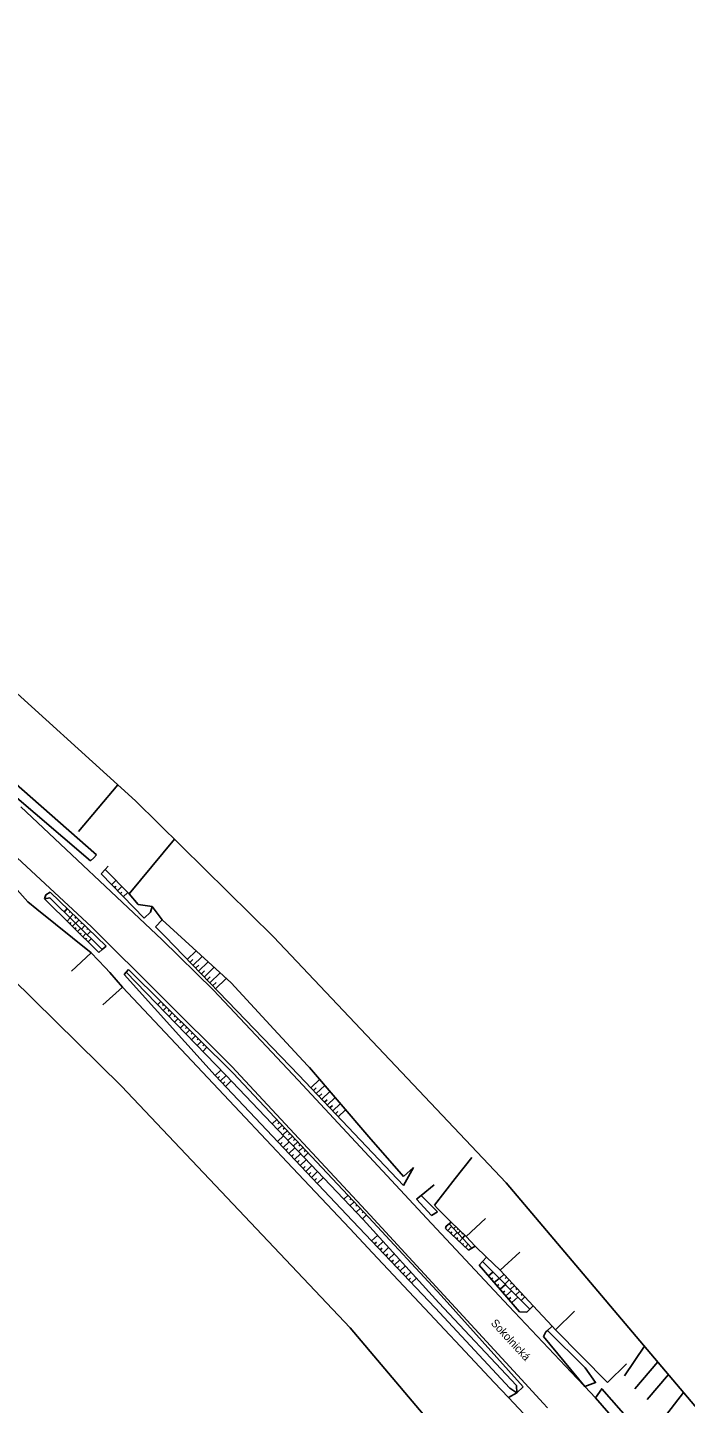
# Model space of a CAD drawing. Extents: x -594451 to -591069, y -1167621 to -1167156.
# Drawn here: x -594264.9 to -594141.4, y -1167414.2 to -1167156.3 of the extents above; entities that cross this region are included whole.
import ezdxf

# ---------------------------------------------------------------- set-up
doc = ezdxf.new("R2010")
doc.units = 0
doc.layers.add('MAPA', color=7, linetype='Continuous')
doc.layers.add('Žádosti', color=7, linetype='Continuous')

msp = doc.modelspace()

# ---------------------------------------------------------------- linework, layer by layer
at = {"layer": 'MAPA'}
for p, q in [((-594247.93, -1167298.31), (-594255.36, -1167307.05)), ((-594245.85, -1167318.7), (-594237.33, -1167308.46)), ((-594152.86, -1167409.05), (-594149.13, -1167403.52)), ((-594150.98, -1167411.48), (-594146.66, -1167406.43)), ((-594144.63, -1167408.84), (-594148.62, -1167413.5)), ((-594145.22, -1167416.56), (-594141.8, -1167412.17))]:
    msp.add_line(p, q, dxfattribs=at)
for points in [[(-594251.95, -1167311.42), (-594267.55, -1167297.72), (-594273.49, -1167293.36), (-594286.83, -1167282.42), (-594286.11, -1167279.61)], [(-594268.63, -1167299.2), (-594253.06, -1167312.5)], [(-594239.69, -1167327.27), (-594266.17, -1167302.4)], [(-594271.2, -1167307.95), (-594252.89, -1167324.93)], [(-594253.06, -1167312.5), (-594252.48, -1167311.94)], [(-594252.48, -1167311.94), (-594251.95, -1167311.42)], [(-594250.33, -1167314.14), (-594251.11, -1167314.98)], [(-594251.11, -1167314.98), (-594243.04, -1167323.26)], [(-594249.74, -1167313.5), (-594250.33, -1167314.14)], [(-594250.33, -1167314.14), (-594245.85, -1167318.7)], [(-594264.81, -1167320.21), (-594266.87, -1167317.96)], [(-594248.31, -1167316.2), (-594249.13, -1167317.01)], [(-594248.31, -1167317.3), (-594248.59, -1167317.57)], [(-594247.2, -1167317.32), (-594248.04, -1167318.13)], [(-594264.81, -1167320.21), (-594263.14, -1167321.56), (-594252.98, -1167329.77)], [(-594261.49, -1167318.88), (-594261.7, -1167319.64)], [(-594260.73, -1167319.48), (-594261.7, -1167319.64)], [(-594261.7, -1167319.64), (-594251.52, -1167329.72)], [(-594260.64, -1167318.42), (-594261.49, -1167318.88)], [(-594250.89, -1167329.17), (-594260.73, -1167319.48)], [(-594250.13, -1167328.52), (-594260.64, -1167318.42)], [(-594247.21, -1167318.43), (-594247.49, -1167318.7)], [(-594246.1, -1167318.44), (-594246.94, -1167319.26)], [(-594245.85, -1167318.7), (-594244.11, -1167320.73)], [(-594244.11, -1167320.73), (-594241.54, -1167321.08)], [(-594258.05, -1167322.12), (-594257.45, -1167321.49)], [(-594256.91, -1167323.24), (-594257.48, -1167323.82)], [(-594257.1, -1167322.23), (-594256.9, -1167322.02)], [(-594256.96, -1167323.19), (-594256.34, -1167322.55)], [(-594256, -1167323.3), (-594255.79, -1167323.08)], [(-594243.04, -1167323.26), (-594241.81, -1167322.16)], [(-594241.81, -1167322.16), (-594241.54, -1167321.08)], [(-594239.66, -1167323.56), (-594241.54, -1167321.08)], [(-594256.8, -1167324.11), (-594256.99, -1167324.31)], [(-594255.92, -1167324.22), (-594256.49, -1167324.8)], [(-594255.8, -1167325.1), (-594256, -1167325.29)], [(-594255.87, -1167324.27), (-594255.24, -1167323.61)], [(-594254.93, -1167325.2), (-594255.5, -1167325.78)], [(-594254.9, -1167324.36), (-594254.69, -1167324.14)], [(-594254.78, -1167325.34), (-594254.13, -1167324.67)], [(-594253.8, -1167325.43), (-594253.58, -1167325.2)], [(-594253.68, -1167326.42), (-594253.03, -1167325.74)], [(-594252.89, -1167324.93), (-594226.57, -1167351.07)], [(-594239.66, -1167323.56), (-594240.9, -1167324.9)], [(-594240.9, -1167324.9), (-594239.04, -1167326.8)], [(-594239.66, -1167323.56), (-594226.69, -1167335.41)], [(-594254.81, -1167326.07), (-594255.01, -1167326.27)], [(-594253.93, -1167326.17), (-594254.51, -1167326.76)], [(-594253.82, -1167327.05), (-594254.02, -1167327.25)], [(-594252.94, -1167327.15), (-594253.52, -1167327.74)], [(-594250.89, -1167329.17), (-594250.13, -1167328.52)], [(-594230.02, -1167336.78), (-594239.69, -1167327.27)], [(-594239.04, -1167326.8), (-594213.98, -1167352.73)], [(-594256.62, -1167333.19), (-594252.98, -1167329.77)], [(-594252.98, -1167329.77), (-594250.3, -1167332.52)], [(-594251.52, -1167329.72), (-594250.89, -1167329.17)], [(-594233.28, -1167329.39), (-594234.96, -1167331.02)], [(-594233.86, -1167331.02), (-594234.43, -1167331.57)], [(-594232.15, -1167330.43), (-594233.9, -1167332.12)], [(-594249.47, -1167333.48), (-594250.3, -1167332.52)], [(-594249.47, -1167333.48), (-594247.06, -1167336.19)], [(-594246.41, -1167333.4), (-594246.75, -1167333.81)], [(-594245.97, -1167332.89), (-594246.41, -1167333.4)], [(-594227.7, -1167352.71), (-594246.41, -1167333.4)], [(-594226.29, -1167352.34), (-594245.97, -1167332.89)], [(-594232.77, -1167332.09), (-594233.37, -1167332.67)], [(-594231.01, -1167331.46), (-594232.84, -1167333.22)], [(-594231.69, -1167333.17), (-594232.3, -1167333.77)], [(-594229.88, -1167332.49), (-594231.77, -1167334.32)], [(-594228.75, -1167333.53), (-594230.71, -1167335.42)], [(-594250.8, -1167339.51), (-594247.06, -1167336.19)], [(-594247.06, -1167336.19), (-594238.07, -1167345.74)], [(-594229.7, -1167352.75), (-594246.75, -1167333.81)], [(-594230.6, -1167334.25), (-594231.24, -1167334.87)], [(-594229.51, -1167335.33), (-594230.18, -1167335.97)], [(-594227.62, -1167334.56), (-594229.65, -1167336.52)], [(-594226.69, -1167335.41), (-594218.67, -1167344.08)], [(-594240.5, -1167339.5), (-594239.9, -1167338.89)], [(-594214.12, -1167353.64), (-594230.02, -1167336.78)], [(-594239.56, -1167339.64), (-594239.35, -1167339.43)], [(-594239.44, -1167340.6), (-594238.81, -1167339.97)], [(-594238.48, -1167340.72), (-594238.27, -1167340.5)], [(-594238.38, -1167341.69), (-594237.73, -1167341.04)], [(-594237.41, -1167341.79), (-594237.19, -1167341.57)], [(-594237.31, -1167342.79), (-594236.64, -1167342.11)], [(-594236.33, -1167342.87), (-594236.1, -1167342.64)], [(-594236.26, -1167343.88), (-594235.56, -1167343.18)], [(-594235.25, -1167343.95), (-594235.02, -1167343.71)], [(-594218.67, -1167344.08), (-594212.34, -1167350.88)], [(-594238.07, -1167345.74), (-594225.06, -1167359.57)], [(-594235.19, -1167344.97), (-594234.48, -1167344.25)], [(-594234.18, -1167345.03), (-594233.94, -1167344.78)], [(-594234.14, -1167346.07), (-594233.39, -1167345.32)], [(-594233.1, -1167346.11), (-594232.85, -1167345.86)], [(-594233.07, -1167347.16), (-594232.31, -1167346.39)], [(-594232.03, -1167347.19), (-594231.77, -1167346.93)], [(-594232.01, -1167348.26), (-594231.23, -1167347.46)], [(-594228.63, -1167351.74), (-594229.7, -1167352.75)], [(-594226.57, -1167351.07), (-594200.58, -1167378.94)], [(-594212.34, -1167350.88), (-594212.01, -1167351.27)], [(-594212.01, -1167351.27), (-594200.89, -1167364.28)], [(-594203.93, -1167379.99), (-594229.7, -1167352.75)], [(-594228.85, -1167352.93), (-594229.21, -1167353.27)], [(-594227.65, -1167352.76), (-594228.72, -1167353.78)], [(-594227.88, -1167353.96), (-594228.24, -1167354.3)], [(-594226.67, -1167353.79), (-594227.75, -1167354.81)], [(-594201.94, -1167379.75), (-594227.7, -1167352.71)], [(-594200.83, -1167379.37), (-594226.29, -1167352.34)], [(-594190, -1167379.57), (-594214.12, -1167353.64)], [(-594213.98, -1167352.73), (-594194.36, -1167373.39)], [(-594210.11, -1167353.49), (-594211.77, -1167355.06)], [(-594210.71, -1167355.09), (-594211.25, -1167355.6)], [(-594209.14, -1167354.63), (-594210.74, -1167356.15)], [(-594209.7, -1167356.19), (-594210.22, -1167356.69)], [(-594208.16, -1167355.77), (-594209.7, -1167357.23)], [(-594207.19, -1167356.91), (-594208.67, -1167358.32)], [(-594225.06, -1167359.57), (-594215.16, -1167370.1)], [(-594208.69, -1167357.3), (-594209.19, -1167357.77)], [(-594207.67, -1167358.4), (-594208.16, -1167358.86)], [(-594206.22, -1167358.05), (-594207.64, -1167359.4)], [(-594206.66, -1167359.5), (-594207.13, -1167359.95)], [(-594205.24, -1167359.19), (-594206.61, -1167360.49)], [(-594219, -1167361.84), (-594218.12, -1167361.01)], [(-594218.01, -1167362.88), (-594217.14, -1167362.06)], [(-594217.92, -1167361.81), (-594217.63, -1167361.53)], [(-594216.89, -1167364.06), (-594218.01, -1167365.11)], [(-594217.02, -1167363.92), (-594216.15, -1167363.1)], [(-594216.94, -1167362.85), (-594216.65, -1167362.58)], [(-594216.03, -1167364.96), (-594215.17, -1167364.14)], [(-594215.95, -1167363.89), (-594215.66, -1167363.62)], [(-594214.97, -1167364.94), (-594214.68, -1167364.67)], [(-594200.89, -1167364.28), (-594194.38, -1167371.72)], [(-594217.1, -1167365.32), (-594217.47, -1167365.68)], [(-594215.82, -1167365.18), (-594216.94, -1167366.24)], [(-594216.03, -1167366.45), (-594216.41, -1167366.8)], [(-594214.75, -1167366.3), (-594215.87, -1167367.37)], [(-594215.05, -1167365.99), (-594214.19, -1167365.19)], [(-594214.06, -1167367.03), (-594213.21, -1167366.23)], [(-594213.98, -1167365.98), (-594213.7, -1167365.71)], [(-594213.07, -1167368.07), (-594212.22, -1167367.27)], [(-594213, -1167367.02), (-594212.71, -1167366.75)], [(-594214.97, -1167367.57), (-594215.34, -1167367.93)], [(-594213.68, -1167367.43), (-594214.81, -1167368.49)], [(-594213.9, -1167368.7), (-594214.28, -1167369.05)], [(-594212.61, -1167368.55), (-594213.74, -1167369.62)], [(-594212.83, -1167369.82), (-594213.21, -1167370.18)], [(-594211.54, -1167369.67), (-594212.68, -1167370.74)], [(-594184.63, -1167372.05), (-594181.54, -1167368.12)], [(-594215.16, -1167370.1), (-594204.45, -1167381.47)], [(-594211.77, -1167370.95), (-594212.14, -1167371.31)], [(-594210.47, -1167370.79), (-594211.61, -1167371.87)], [(-594210.7, -1167372.07), (-594211.08, -1167372.43)], [(-594209.4, -1167371.92), (-594210.55, -1167373)], [(-594194.38, -1167371.72), (-594192.46, -1167370.01)], [(-594194.36, -1167373.39), (-594192.46, -1167370.01)], [(-594188.56, -1167377.06), (-594184.63, -1167372.05)], [(-594188.6, -1167373.24), (-594191.03, -1167375.24)], [(-594205.56, -1167375.95), (-594204.76, -1167375.19)], [(-594204.45, -1167376.06), (-594204.18, -1167375.81)], [(-594204.4, -1167377.17), (-594203.6, -1167376.43)], [(-594203.28, -1167377.29), (-594203.02, -1167377.04)], [(-594191.03, -1167375.24), (-594191.91, -1167375.96)], [(-594191.91, -1167375.96), (-594189.07, -1167379.02)], [(-594191.03, -1167375.24), (-594187.96, -1167378.31)], [(-594187.97, -1167377.72), (-594188.56, -1167377.06)], [(-594188.4, -1167396.29), (-594203.93, -1167379.99)], [(-594203.23, -1167378.4), (-594202.44, -1167377.66)], [(-594202.12, -1167378.52), (-594201.86, -1167378.28)], [(-594202.06, -1167379.63), (-594201.28, -1167378.89)], [(-594187.71, -1167395.36), (-594201.94, -1167379.75)], [(-594187.3, -1167394), (-594200.83, -1167379.37)], [(-594200.58, -1167378.94), (-594171.51, -1167410.53)], [(-594161.82, -1167409.49), (-594174.58, -1167396.03), (-594190, -1167379.57)], [(-594189.07, -1167379.02), (-594187.96, -1167378.31)], [(-594187.97, -1167377.72), (-594185.41, -1167380.26)], [(-594182.61, -1167382.95), (-594178.94, -1167379.55)], [(-594204.45, -1167381.47), (-594200.18, -1167386.01)], [(-594199.23, -1167382.73), (-594200.33, -1167383.77)], [(-594186.32, -1167381), (-594186.45, -1167381.42)], [(-594186.45, -1167381.42), (-594182.15, -1167385.54)], [(-594185.81, -1167380.59), (-594186.32, -1167381)], [(-594185.35, -1167381.08), (-594186.05, -1167381.81)], [(-594185.41, -1167380.26), (-594185.81, -1167380.59)], [(-594185.81, -1167380.59), (-594181.52, -1167385.13)], [(-594185.27, -1167382.1), (-594185.5, -1167382.33)], [(-594182.61, -1167382.95), (-594185.41, -1167380.26)], [(-594184.96, -1167381.49), (-594184.56, -1167381.07)], [(-594184.3, -1167382.18), (-594184.95, -1167382.86)], [(-594184.27, -1167381.64), (-594184.13, -1167381.49)], [(-594184.13, -1167382.37), (-594183.69, -1167381.91)], [(-594183.41, -1167382.49), (-594183.25, -1167382.33)], [(-594183.3, -1167383.25), (-594182.82, -1167382.75)], [(-594199.43, -1167383.99), (-594199.79, -1167384.33)], [(-594198.18, -1167383.87), (-594199.26, -1167384.9)], [(-594198.37, -1167385.12), (-594198.72, -1167385.46)], [(-594197.14, -1167385.02), (-594198.18, -1167386.02)], [(-594184.19, -1167383.17), (-594184.4, -1167383.39)], [(-594183.26, -1167383.29), (-594183.85, -1167383.91)], [(-594183.11, -1167384.24), (-594183.3, -1167384.44)], [(-594182.21, -1167384.4), (-594182.75, -1167384.96)], [(-594180.93, -1167384.76), (-594182.61, -1167382.95)], [(-594182.15, -1167385.54), (-594181.52, -1167385.13)], [(-594181.52, -1167385.13), (-594180.93, -1167384.76)], [(-594180.93, -1167384.76), (-594178.81, -1167386.84)], [(-594200.18, -1167386.01), (-594190.43, -1167396.37)], [(-594197.3, -1167386.25), (-594197.65, -1167386.58)], [(-594196.09, -1167386.17), (-594197.11, -1167387.15)], [(-594196.24, -1167387.39), (-594196.58, -1167387.71)], [(-594195.04, -1167387.32), (-594196.04, -1167388.27)], [(-594180.17, -1167388.35), (-594178.81, -1167386.84)], [(-594179.54, -1167387.66), (-594170.63, -1167396.58)], [(-594176.19, -1167389.26), (-594178.81, -1167386.84)], [(-594176.19, -1167389.26), (-594172.52, -1167385.86)], [(-594195.18, -1167388.52), (-594195.51, -1167388.83)], [(-594194, -1167388.46), (-594194.97, -1167389.39)], [(-594194.12, -1167389.65), (-594194.44, -1167389.96)], [(-594192.95, -1167389.61), (-594193.9, -1167390.52)], [(-594180.17, -1167388.35), (-594172.56, -1167397.05)], [(-594177.59, -1167389.62), (-594178.42, -1167390.35)], [(-594176.37, -1167390.84), (-594175.49, -1167390.02)], [(-594170, -1167395.94), (-594176.19, -1167389.26)], [(-594193.05, -1167390.78), (-594193.37, -1167391.08)], [(-594191.9, -1167390.76), (-594192.83, -1167391.64)], [(-594177.58, -1167390.72), (-594177.87, -1167390.97)], [(-594176.41, -1167390.8), (-594177.33, -1167391.6)], [(-594176.46, -1167391.94), (-594176.78, -1167392.22)], [(-594175.23, -1167391.97), (-594176.24, -1167392.85)], [(-594175.35, -1167391.86), (-594174.5, -1167391.08)], [(-594175.28, -1167390.82), (-594175, -1167390.55)], [(-594174.32, -1167392.88), (-594173.52, -1167392.14)], [(-594174.29, -1167391.86), (-594174.01, -1167391.61)], [(-594173.29, -1167392.91), (-594173.03, -1167392.67)], [(-594173.15, -1167410.89), (-594187.71, -1167395.36)], [(-594171.9, -1167411.13), (-594187.3, -1167394)], [(-594175.34, -1167393.17), (-594175.69, -1167393.47)], [(-594174.06, -1167393.15), (-594175.14, -1167394.1)], [(-594174.22, -1167394.4), (-594174.6, -1167394.72)], [(-594172.88, -1167394.33), (-594174.05, -1167395.35)], [(-594173.3, -1167393.9), (-594172.54, -1167393.2)], [(-594172.3, -1167393.96), (-594172.05, -1167393.73)], [(-594172.28, -1167394.93), (-594171.56, -1167394.26)], [(-594190.43, -1167396.37), (-594185.65, -1167401.45)], [(-594174.42, -1167411.4), (-594188.4, -1167396.29)], [(-594172.56, -1167397.05), (-594171.19, -1167397.16)], [(-594171.19, -1167397.16), (-594170, -1167395.94)], [(-594170, -1167395.94), (-594166.48, -1167399.77)], [(-594165.85, -1167400.42), (-594162.26, -1167396.94)], [(-594167.66, -1167400.85), (-594168.08, -1167401.68)], [(-594167.34, -1167400.56), (-594167.66, -1167400.85)], [(-594166.48, -1167399.77), (-594167.34, -1167400.56)], [(-594167.34, -1167400.56), (-594160.24, -1167407.57)], [(-594165.85, -1167400.42), (-594166.48, -1167399.77)], [(-594156.1, -1167410.3), (-594165.85, -1167400.42)], [(-594185.65, -1167401.45), (-594184.59, -1167402.58)], [(-594184.59, -1167402.58), (-594177.33, -1167410.29)], [(-594160.3, -1167411.07), (-594168.08, -1167401.68)], [(-594160.24, -1167407.57), (-594158.3, -1167410.34), (-594160.3, -1167411.07)], [(-594156.1, -1167410.3), (-594152.54, -1167406.79)], [(-594177.33, -1167410.29), (-594174.67, -1167413.11), (-594170.81, -1167417.21), (-594169.82, -1167418.27), (-594166.97, -1167421.65)], [(-594173.06, -1167412.28), (-594173.15, -1167410.89)], [(-594173.06, -1167412.28), (-594171.9, -1167411.13)], [(-594171.51, -1167410.53), (-594168.14, -1167414.19), (-594167.31, -1167415.09)], [(-594161.82, -1167409.49), (-594160.3, -1167411.07), (-594158.31, -1167413.17), (-594141.24, -1167432.82), (-594130, -1167446.23), (-594125.84, -1167451.9)], [(-594174.67, -1167413.11), (-594173.06, -1167412.28)], [(-594173.06, -1167412.28), (-594174.42, -1167411.4)], [(-594158.31, -1167413.17), (-594157.15, -1167411.48), (-594147.63, -1167422.29), (-594139.53, -1167431.49)]]:
    msp.add_lwpolyline(points, dxfattribs=at)
at = {"layer": 'Žádosti'}
msp.add_lwpolyline([(-593986.37, -1167595.74), (-594017.13, -1167621.31), (-594204.39, -1167400.1), (-594247.28, -1167354.77), (-594272.08, -1167330.4), (-594298.05, -1167306.9), (-594450.5, -1167187.84), (-594425.88, -1167156.32), (-594272.29, -1167276.27), (-594244.63, -1167301.29), (-594218.73, -1167326.75), (-594175.06, -1167372.9)], close=True, dxfattribs=at)

# ---------------------------------------------------------------- texts
at = {"layer": 'MAPA'}
msp.add_text('Sokolnická', height=1.5, rotation=312.62, dxfattribs=at).set_placement((-594178.07, -1167399.26))

doc.saveas('drawing.dxf')
